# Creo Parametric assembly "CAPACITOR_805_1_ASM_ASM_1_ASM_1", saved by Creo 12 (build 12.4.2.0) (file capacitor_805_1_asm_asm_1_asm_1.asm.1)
Units: Custom; MM, KILOGRAM, SECS

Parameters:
  PTC_WM_ITERATION = "0"
  PTC_WM_VERSION = "-.0"
  PTC_WM_LIFECYCLE_STATE = "In Work"
  PTC_WM_LIFECYCLE = "MO_CADDocument"
  PTC_WM_CREATED_BY = "Maximilian Roepper (Z0017RMS: MO)"
  PTC_WM_CREATED_ON = "18-Sep-26 11:36:42 AM"
  PTC_WM_MODIFIED_BY = "Maximilian Roepper (Z0017RMS: MO)"
  PTC_WM_MODIFIED_ON = "18-Sep-26 11:36:46 AM"
  PDMLINKNUMBER = "PDM000071455288"
  PTC_WM_NUMBER = "PDM000071455288"

Other parameters: WEIGHT, WEIGHT_FACTOR, WEIGHT_ADD, MC_ERRORS, SUPPLIER

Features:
  1. coordinate system
  2. imported feature
  3. component "VALOR_PREDETERMINADO_5_PRT_1__1"

Other named items: DRW_VIEW_ORG, ROUGH-GROB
